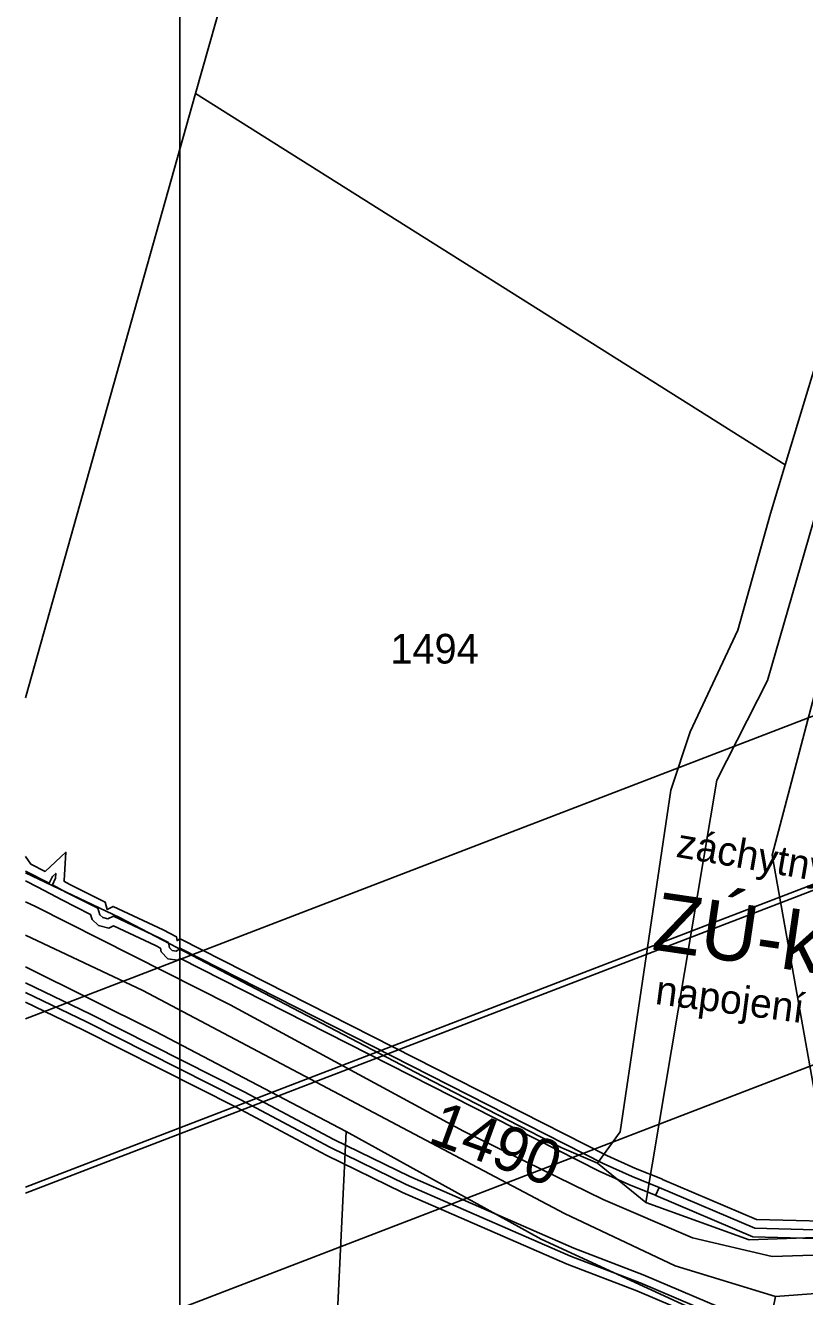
# Model space of a CAD drawing. Extents: x -510185 to -506993, y -1126306 to -1123642.
# Drawn here: x -510185 to -510051.1, y -1125355.5 to -1125137 of the extents above; entities that cross this region are included whole.
import ezdxf

# ---------------------------------------------------------------- set-up
doc = ezdxf.new("R2010")
doc.units = 0
for name, color, linetype in [('parcelni hranice', 7, 'Continuous'), ('popis cesty', 7, 'Continuous'), ('telefonica', 7, 'Continuous'), ('u_Telefonica', 7, 'Continuous'), ('u_ČEPS nadzemní VVN', 7, 'Continuous'), ('x_formát_rám', 7, 'Continuous'), ('ČEPS', 7, 'Continuous'), ('ˇ2', 7, 'Continuous'), ('ˇ4', 7, 'Continuous')]:
    doc.layers.add(name, color=color, linetype=linetype)

msp = doc.modelspace()

# ---------------------------------------------------------------- linework, layer by layer
at = {"layer": 'parcelni hranice'}
for p, q in [((-510011.81, -1125091.56), (-510057.49, -1125249.6)), ((-510155.81, -1125148.73), (-510147, -1125117.44)), ((-510054.45, -1125212.57), (-510030.93, -1125134.76)), ((-510185.05, -1125252.6), (-510155.81, -1125148.73)), ((-510155.81, -1125148.73), (-510054.45, -1125212.57)), ((-510056.98, -1125220.93), (-510054.45, -1125212.57)), ((-510062.57, -1125241), (-510056.98, -1125220.93)), ((-510042.33, -1125225.09), (-510056.66, -1125279.65)), ((-510070.77, -1125258.45), (-510062.57, -1125241)), ((-510066.17, -1125266.74), (-510057.49, -1125249.6)), ((-510074.07, -1125268.45), (-510070.77, -1125258.45)), ((-510078.42, -1125339.36), (-510066.17, -1125266.74)), ((-510074.07, -1125268.45), (-510076.95, -1125287.81)), ((-510046.07, -1125339.12), (-510056.66, -1125279.65)), ((-510185.05, -1125282.66), (-510168.85, -1125290.35)), ((-510076.95, -1125287.81), (-510082.8, -1125327.21)), ((-510116.72, -1125317.62), (-510168.85, -1125290.35)), ((-510164.84, -1125302.93), (-510185.05, -1125293.42)), ((-510185.05, -1125298.82), (-510162.7, -1125309.97)), ((-510164.84, -1125302.93), (-510092.35, -1125341.25)), ((-510162.7, -1125309.97), (-510129.92, -1125327.14)), ((-510092.86, -1125329.94), (-510116.72, -1125317.62)), ((-510132.16, -1125373.62), (-510129.92, -1125327.14)), ((-510096.36, -1125345.63), (-510129.92, -1125327.14)), ((-510082.8, -1125327.21), (-510086.72, -1125332.59)), ((-510092.86, -1125329.94), (-510086.72, -1125332.59)), ((-510086.72, -1125332.59), (-510078.42, -1125339.36)), ((-510092.35, -1125341.25), (-510073.35, -1125350.24)), ((-510078.42, -1125339.36), (-510060.65, -1125345.74)), ((-510096.36, -1125345.63), (-510071.49, -1125357.11)), ((-510060.65, -1125345.74), (-510044.98, -1125345.22)), ((-510056.1, -1125355.49), (-510073.35, -1125350.24)), ((-510056.1, -1125355.49), (-510057.09, -1125360.29))]:
    msp.add_line(p, q, dxfattribs=at)
at = {"layer": 'telefonica'}
for points in [[(-510185.05, -1125279.85), (-510185.04, -1125279.85), (-510184.13, -1125281.18), (-510181.64, -1125282.44), (-510181.64, -1125282.44), (-510178.08, -1125279.15), (-510178.39, -1125283.99), (-510178.44, -1125284.11), (-510177.41, -1125284.67), (-510171.36, -1125287.72), (-510170.98, -1125288.97), (-510169.94, -1125288.46), (-510161.39, -1125292.51), (-510159.09, -1125293.68), (-510158.98, -1125294.33), (-510158.42, -1125294.02), (-510085.1, -1125331.29), (-510080.15, -1125333.52), (-510075.53, -1125335.36)], [(-510185.05, -1125284.08), (-510182.93, -1125285.15), (-510179.74, -1125286.82), (-510178.8, -1125287.32), (-510173.85, -1125289.82), (-510173.58, -1125290.73), (-510172.48, -1125291.76), (-510170.73, -1125292.18), (-510169.92, -1125291.79), (-510162.71, -1125295.2), (-510161.8, -1125295.66), (-510161.7, -1125296.28), (-510160.56, -1125297.45), (-510158.88, -1125297.69), (-510158.37, -1125297.41), (-510086.4, -1125333.99), (-510081.32, -1125336.28), (-510076.64, -1125338.15)], [(-510185.05, -1125301.6), (-510173.86, -1125306.97), (-510147.43, -1125320.32), (-510132.01, -1125328.51), (-510118.95, -1125334.9), (-510090.75, -1125347.18), (-510078.83, -1125351.78), (-510057.12, -1125360.99)], [(-510185.05, -1125304.92), (-510175.18, -1125309.67), (-510148.81, -1125322.98), (-510133.37, -1125331.19), (-510120.21, -1125337.62), (-510091.89, -1125349.96), (-510079.95, -1125354.56), (-510058.26, -1125363.77)], [(-510075.5, -1125335.37), (-510059.36, -1125342.25), (-510041.22, -1125342.74), (-510023.98, -1125335.75), (-510022.65, -1125335.21)], [(-510076.67, -1125338.14), (-510060.01, -1125345.23), (-510040.67, -1125345.76), (-510022.85, -1125338.53), (-510021.53, -1125337.99)]]:
    msp.add_lwpolyline(points, dxfattribs=at)
at = {"layer": 'u_Telefonica'}
msp.add_line((-510076.09, -1125336.76), (-510076.71, -1125338.13), dxfattribs=at)
msp.add_line((-510076.09, -1125336.76), (-510076.71, -1125338.13), dxfattribs=at)
for points in [[(-510185.05, -1125282.4), (-510180.95, -1125284.47), (-510180.41, -1125283.34), (-510179.82, -1125282.79), (-510179.87, -1125283.6), (-510180.41, -1125284.75), (-510178.11, -1125286), (-510172.61, -1125288.77), (-510172.26, -1125289.91), (-510171.74, -1125290.39), (-510170.9, -1125290.6), (-510169.93, -1125290.12), (-510162.05, -1125293.86), (-510160.44, -1125294.67), (-510160.3, -1125295.57), (-510159.84, -1125296.03), (-510159.16, -1125296.13), (-510158.39, -1125295.71), (-510085.75, -1125332.64), (-510080.73, -1125334.9), (-510076.09, -1125336.76)], [(-510185.05, -1125282.4), (-510180.95, -1125284.47), (-510180.41, -1125283.34), (-510179.82, -1125282.79), (-510179.87, -1125283.6), (-510180.41, -1125284.75), (-510178.11, -1125286), (-510172.61, -1125288.77), (-510172.26, -1125289.91), (-510171.74, -1125290.39), (-510170.9, -1125290.6), (-510169.93, -1125290.12), (-510162.05, -1125293.86), (-510160.44, -1125294.67), (-510160.3, -1125295.57), (-510159.84, -1125296.03), (-510159.16, -1125296.13), (-510158.39, -1125295.71), (-510085.75, -1125332.64), (-510080.73, -1125334.9), (-510076.09, -1125336.76)], [(-510185.05, -1125303.26), (-510174.52, -1125308.32), (-510148.12, -1125321.65), (-510132.69, -1125329.85), (-510119.58, -1125336.26), (-510091.32, -1125348.57), (-510079.39, -1125353.17), (-510057.69, -1125362.38)], [(-510185.05, -1125303.26), (-510174.52, -1125308.32), (-510148.12, -1125321.65), (-510132.69, -1125329.85), (-510119.58, -1125336.26), (-510091.32, -1125348.57), (-510079.39, -1125353.17), (-510057.69, -1125362.38)], [(-510185.05, -1125303.26), (-510174.52, -1125308.32), (-510148.12, -1125321.65), (-510132.69, -1125329.85), (-510119.58, -1125336.26), (-510091.32, -1125348.57), (-510079.39, -1125353.17), (-510057.69, -1125362.38)], [(-510185.05, -1125303.26), (-510174.52, -1125308.32), (-510148.12, -1125321.65), (-510132.69, -1125329.85), (-510119.58, -1125336.26), (-510091.32, -1125348.57), (-510079.39, -1125353.17), (-510057.69, -1125362.38)], [(-510076.09, -1125336.76), (-510059.68, -1125343.74), (-510040.95, -1125344.25), (-510023.42, -1125337.14), (-510022.09, -1125336.6)], [(-510076.09, -1125336.76), (-510059.68, -1125343.74), (-510040.95, -1125344.25), (-510023.42, -1125337.14), (-510022.09, -1125336.6)]]:
    msp.add_lwpolyline(points, dxfattribs=at)
at = {"layer": 'u_ČEPS nadzemní VVN'}
for points in [[(-510185.05, -1125336.69), (-510011.44, -1125269.94), (-509690.54, -1125194.07), (-509367.08, -1125118.37), (-509051.23, -1125043.52), (-508723.83, -1124966.6), (-508395.54, -1124892.88), (-508077.37, -1124819.87), (-507910.72, -1124779.68)], [(-510185.05, -1125337.76), (-510011.14, -1125270.9), (-509690.31, -1125195.05), (-509366.85, -1125119.34), (-509051.01, -1125044.5), (-508723.61, -1124967.57), (-508395.32, -1124893.85), (-508077.14, -1124820.84), (-507910.72, -1124780.71)]]:
    msp.add_lwpolyline(points, dxfattribs=at)
at = {"layer": 'x_formát_rám'}
msp.add_lwpolyline([(-510158.52, -1126278.21), (-507008.52, -1126278.21), (-507008.52, -1123673.61), (-510158.52, -1123673.61)], close=True, dxfattribs=at)
at = {"layer": 'ČEPS'}
for points in [[(-510185.05, -1125307.76), (-510019.43, -1125244.08), (-509696.72, -1125167.79), (-509373.27, -1125092.09), (-509057.44, -1125017.25), (-508729.88, -1124940.28), (-508401.51, -1124866.55), (-508083.55, -1124793.59), (-507890, -1124746.91)], [(-510185.05, -1125367.76), (-510002.86, -1125297.71), (-509683.9, -1125222.3), (-509360.43, -1125146.6), (-509044.57, -1125071.75), (-508717.34, -1124994.86), (-508389.12, -1124921.16), (-508070.72, -1124848.1), (-507890, -1124804.52)]]:
    msp.add_lwpolyline(points, dxfattribs=at)
at = {"layer": 'ˇ4'}
for p, q in [((-510183.3, -1125288.5), (-510185.05, -1125287.67)), ((-510149.87, -1125305.39), (-510183.3, -1125288.5)), ((-510109.74, -1125327.07), (-510149.87, -1125305.39)), ((-510085.73, -1125338.84), (-510109.74, -1125327.07)), ((-510070.35, -1125345.44), (-510085.73, -1125338.84)), ((-510056.67, -1125348.63), (-510070.35, -1125345.44)), ((-510042.46, -1125348.13), (-510056.67, -1125348.63)), ((-510041.84, -1125354.41), (-510056.1, -1125355.49))]:
    msp.add_line(p, q, dxfattribs=at)

# ---------------------------------------------------------------- texts
at = {"layer": 'popis cesty'}
for s, height, rotation, p in [('záchytný žlab', 5, 350.2367, (-510073.36, -1125279.92)), ('ZÚ-km 0,003 ', 10, 351.6845, (-510077.55, -1125295.84)), ('napojení na stát. silnici ', 5, 352.5844, (-510076.94, -1125305.21))]:
    msp.add_text(s, height=height, rotation=rotation, dxfattribs=at).set_placement(p)
at = {"layer": 'ˇ2'}
msp.add_text('1494', height=5.1, dxfattribs=at).set_placement((-510122.3, -1125246.71))
msp.add_text('1490', height=7.65, rotation=339.8637, dxfattribs=at).set_placement((-510116.1, -1125328.91))

doc.saveas('drawing.dxf')
